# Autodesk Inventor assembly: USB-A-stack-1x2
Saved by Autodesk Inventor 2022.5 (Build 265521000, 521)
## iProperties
Created: 2024-12
Part Number: USB-A-stack-1x2
Document SubType Name: Assembly
Designer: AdminForWorker
Title: USB-A-stack-1x2 v1
Author: AdminForWorker
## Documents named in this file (4)
- c:\worker\convert-fusion-r05-cosv3\tmp\job-1\35\temp\files\545dca92-a972-481a-9197-dd1a1176500e\USB-A-stack-1x2 v1_1.iam
- c:\worker\convert-fusion-r05-cosv3\tmp\job-1\35\temp\files\545dca92-a972-481a-9197-dd1a1176500e\shell_1.iam
- c:\worker\convert-fusion-r05-cosv3\tmp\job-1\35\temp\files\545dca92-a972-481a-9197-dd1a1176500e\Component4_1.iam
- c:\worker\convert-fusion-r05-cosv3\tmp\job-1\35\temp\files\545dca92-a972-481a-9197-dd1a1176500e\leads_2.iam
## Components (3 placed, 3 different names)
1. shell:1 [sub-assembly]
2. Component4:1 [sub-assembly]
3. leads:1 [sub-assembly]
